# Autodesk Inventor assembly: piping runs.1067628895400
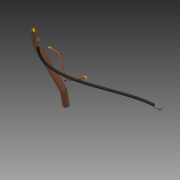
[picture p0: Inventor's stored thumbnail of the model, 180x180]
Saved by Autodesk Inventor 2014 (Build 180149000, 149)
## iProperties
Name: Hydraulic Hose - SAE Flanged Connection
ActiveState: False
PipeType: Flexible Hose
Material: UnInitValue
Standard: UnInitValue
FittingMaterial: UnInitValue
FittingStandard: UnInitValue
RouteDirection90: UnInitValue
RouteDirection45: UnInitValue
DiameterType: Nominal
Diameter: 1/2
Schedule: ID=0.5
OD: 0.880 in
ID: 0.500 in
Ending: UnInitValue
RoundUpValue: 0.125 in
DefaultBendRadius: UnInitValue
BendRadius: 0.500 in
PipingComponentColor: As Material
PipeKey: v3#d489867e-ac9b-47ea-b952-0a1b885f66be#4
CouplingKey: UnInitValue
StartFittingKey: v3#933069c9-73b6-4141-af99-628d4a97b2c2#1
EndFittingKey: v3#933069c9-73b6-4141-af99-628d4a97b2c2#1
Elbow90Key: UnInitValue
Elbow45Key: UnInitValue
SuppressStartFitting: False
SuppressEndFitting: False
UseSubASM: True
_ComponentInfo: <CS><C N="Pipe" R="1.117600" OR="1.117600" IR="0.635000" PL="PL" PartType="pipe" SymKey="" PN="Parker Hydraulic Hose - No Skive 1/2"><CO N="1"><FE V="0"/><FD V=
FlangeKey: UnInitValue
Gap: UnInitValue
GasketKey: UnInitValue
IsButtWelded: UnInitValue
IsFlanged: UnInitValue
MixedUnits: UnInitValue
ShowGap: UnInitValue
UseFlangsForCouplings: UnInitValue
Angle: UnInitValue
ElbowCustomKey: UnInitValue
IsSelfDraining: UnInitValue
Name: Hydraulic Hose - Male Taper Thread
StartFittingKey: v3#c8250148-a7b6-458b-b7bd-3b56763ca7cc#11
EndFittingKey: v3#c8250148-a7b6-458b-b7bd-3b56763ca7cc#11
Name: JIS G 3458/JIS B 2316 -  Welded Steel Pipe and Fittings
PipeType: Rigid Pipe
RouteDirection90: True
RouteDirection45: True
Diameter: M40
Schedule: 80
OD: UnInitValue
ID: UnInitValue
IntermediateSegmentsMin: 2.362 in
IntermediateSegmentsMax: 196.850 in
IntermediateSegmentsInc: 0.039 in
TerminationSegmentsMin: 2.362 in
TerminationSegmentsMax: 196.850 in
TerminationSegmentsInc: 0.039 in
PipeKey: v3#da14b0ab-0b36-4851-8d66-8c9cd0bcbe86#23
CouplingKey: v3#12b64993-10e6-4915-8315-0c0cce209ad0#16
Elbow90Key: v3#1f65ece3-c41a-48d4-8661-909ed34ade86#16
Elbow45Key: v3#28e76e79-e22c-40ab-8be2-ff545b1407c5#16
_ComponentInfo: <CS><C N="Pipe" R="2.430000" OR="2.430000" IR="1.920000" PL="PL" PartType="pipe" SymKey="" PN="JIS G 3458 Pipe 40 A x Sch 80"><CO N="1"><FE V="2"/><FD V="1"/><E
BendRadius: UnInitValue
EndFittingKey: UnInitValue
IsButtWelded: False
IsFlanged: False
MixedUnits: False
RoundUpValue: UnInitValue
StartFittingKey: UnInitValue
SuppressEndFitting: UnInitValue
SuppressStartFitting: UnInitValue
UseSubASM: UnInitValue
IsSelfDraining: False
Name: Hydraulic Hose - Male Straight Thread
StartFittingKey: v3#b50cb43e-68c0-48ac-8e25-7ef224ce0e6c#3
EndFittingKey: v3#b50cb43e-68c0-48ac-8e25-7ef224ce0e6c#3
Name: Hydraulic Hose - No Fittings
SuppressStartFitting: True
SuppressEndFitting: True
Diameter: 6
Elbow90Key: v3#97ecdcaf-8aa3-4fb0-8b6a-3da783de2ad5#108
Gap: 0.062 in
IntermediateSegmentsInc: 0.000 in
IntermediateSegmentsMax: 200.000 in
IntermediateSegmentsMin: 3.000 in
IsButtWelded: True
Name: ASTM A 53/A-ASME B16.9 - Steel Butt Welded Pipe
PipeKey: v3#4ce5e9fa-6da0-4801-ac02-ee7a0fb518d6#77
RouteDirection45: False
Schedule: 40
ShowGap: True
TerminationSegmentsInc: 0.000 in
TerminationSegmentsMax: 200.000 in
TerminationSegmentsMin: 3.000 in
_ComponentInfo: <CS><C N="Pipe" R="8.413750" OR="8.413750" IR="7.702550" PL="PL" PartType="pipe" SymKey="" PN="ASTM A 53/A 53M Pipe 6 - Schedule 40"><CO N="1"><FE V="2"/><FD V=
Company: Autodesk, Inc.
Name: ASME B36.10M-ASME B16.11 - Steel Threaded Pipe
Schedule: 30
IntermediateSegmentsMin: 2.000 in
IntermediateSegmentsInc: 0.100 in
TerminationSegmentsMin: 2.000 in
TerminationSegmentsInc: 0.100 in
PipeKey: v3#4a736116-503a-44ad-a922-868ac6b46736#1
CouplingKey: v3#52ad3977-2b89-4007-a6a6-7626bac0ae85#4
Elbow90Key: v3#160eac10-3e6f-4b5c-839c-61eee0d373dc#4
Elbow45Key: v3#5c2ab816-abcb-49a6-a106-4733af000f51#4
_ComponentInfo: <CS><C N="Pipe" R="1.066800" OR="1.066800" IR="0.825500" PL="PL" PartType="pipe" SymKey="" PN="ASME B36.10M Pipe with Threaded Ends 1/2 - Schedule 30"><CO N="1"
Name: ASTM A53/A53M-ASME B16.11 - Welded Steel Pipe
IntermediateSegmentsMin: 1.000 in
TerminationSegmentsMin: 1.000 in
PipeKey: v3#4ce5e9fa-6da0-4801-ac02-ee7a0fb518d6#7
CouplingKey: v3#ed415c76-4cec-44a3-ba67-72e47bf70384#4
Elbow90Key: v3#82a08401-12d7-413b-b7f9-9cf3b607be7b#4
Elbow45Key: v3#2e5fd082-3851-4eb0-bde1-6c7078a7d72b#4
_ComponentInfo: <CS><C N="Pipe" R="1.066800" OR="1.066800" IR="0.789940" PL="PL" PartType="pipe" SymKey="" PN="ASTM A 53/A 53M Pipe 1/2 - Schedule 40"><CO N="1"><FE V="2"/><FD 
Name: ISO 2531 - Flanged Ductile Iron Pipe and Fittings
Schedule: PN10
IntermediateSegmentsMin: 39.370 in
IntermediateSegmentsMax: 354.331 in
IntermediateSegmentsInc: 0.394 in
TerminationSegmentsMin: 39.370 in
TerminationSegmentsMax: 354.331 in
TerminationSegmentsInc: 0.394 in
PipeKey: v3#f52fbdcb-ece8-4303-8b76-5dbe8c7f2f9c#16
Elbow90Key: v3#451ae64e-c79d-4cba-b533-c09b8090ecb2#1
Elbow45Key: v3#81684a3f-f2a4-4fe6-95b1-f067ddead22f#1
_ComponentInfo: <CS><C N="Pipe" R="2.700000" OR="2.700000" IR="2.000000" PL="PL" PartType="pipe" SymKey="" PN="ISO 2531 Pipe with Integrally Cast Flanges DN40 PN 10"><CO N="1">
Name: Hydraulic Hose - Female Thread - Swivel
StartFittingKey: v3#c5e461f5-5e73-4f2e-8c1e-4358d4d6f46c#4
EndFittingKey: v3#c5e461f5-5e73-4f2e-8c1e-4358d4d6f46c#4
USE_R9_BOM: False
TPVersion: 11.0.2
Name: DIN 2458/DIN 2605 - Welded Steel Pipe and Fittings
Schedule: ID=30.7
PipeKey: v3#dcef2839-8903-4c98-a96c-b861f5d9bb7f#98
Elbow90Key: v3#ace818b0-7b7c-4ad9-b19c-6da358a202c1#17
Elbow45Key: v3#97879d80-057e-491b-840b-74a9b3a7cf63#17
_ComponentInfo: <CS><C N="Pipe" R="2.415000" OR="2.415000" IR="1.535000" PL="PL" PartType="pipe" SymKey="" PN="DIN 2458 Pipe 48.3 x 8.8"><CO N="1"><FE V="2"/><FD V="0"/><ET V="
Control State: 0
Master: False
Checked Out: False
Angle: 92.00 deg
Diameter: 1
Elbow45Key: v3#bf26aa2a-f3dd-474c-8758-922a145c2b02#15
Elbow90Key: v3#3e93288f-9bb7-4e46-9d6b-544f8c20ca1c#3
ElbowCustomKey: v3#1f3bd44a-47ab-42f9-b3e0-74afa0c3f0ca#3
Gap: 0.094 in
IsSelfDraining: True
Name: ASME BPE - Butt Welded
PipeKey: v3#b10c956f-6fc6-429e-8056-0864a8581764#39
Schedule: ID=0.76
_ComponentInfo: <CS><C N="Pipe" R="1.270000" OR="1.270000" IR="0.965200" PL="PL" PartType="pipe" SymKey="" PN="ASTM A 269 Tube with Welded ends 1 x 0.12"><CO N="1"><FE V="2"/><
Elbow90Key: v3#6a678020-d9d9-4685-bba9-906b9a167083#10
FlangeKey: v3#24991861-26e3-4c21-a713-f46e314eddd5#10
GasketKey: v3#2a41914c-f5fb-4682-9c6a-1870d826d3d0#23
IsFlanged: True
Name: ASTM A 53/A 53M - Butt Welded/Flanged Steel Pipe
UseFlangsForCouplings: False
Name: JIS G 3442/JIS B 2301 Threaded Steel Pipe and Iron Fittings
Schedule: ID=16.1
IntermediateSegmentsMin: 0.787 in
TerminationSegmentsMin: 0.787 in
PipeKey: v3#9964fba4-9d5a-4d75-85a8-e38022ccdce1#2
CouplingKey: v3#181262db-c004-4877-bc40-c64b931a44f6#3
Elbow90Key: v3#6c92b367-65e9-486b-b952-db434ae2548d#3
Elbow45Key: v3#960407aa-00b9-4d72-aae7-d50595845cfd#3
_ComponentInfo: <CS><C N="Pipe" R="1.085000" OR="1.085000" IR="0.805000" PL="PL" PartType="pipe" SymKey="" PN="JIS G 3442 Pipe with Threaded Ends 21.7 x 2.8"><CO N="1"><FE V="0
Name: Large Copper Tubing
PipeType: Tubing
Diameter: 2
Schedule: L
IntermediateSegmentsMin: 0.000 in
IntermediateSegmentsMax: 100.000 in
TerminationSegmentsMin: 0.000 in
TerminationSegmentsMax: 100.000 in
DefaultBendRadius: 2.000 in
PipeKey: V3#44B182C9-4BCE-4825-BB4D-596143122252#24
CouplingKey: V3#0DC1AE02-7BBF-4CCF-8498-581434B0A765#8
_ComponentInfo: <CS><C N="Pipe" R="2.698750" OR="2.698750" IR="2.520950" PL="PL" PartType="pipe" SymKey="" PN="ASTM B 88 Tube 2 - Type L"><CO N="1"><FE V="0"/><FD V="0"/><ET V=
Part Number: piping runs.1067628895400
Document SubType Name: Tube & Pipe
Created: 2003-10
Designer: Autodesk, Inc.
Manufacturer: Standard
Standards Organization: Custom
Mass: 2522.31 g
Surface Area: 4231.74 cm^2
Volume: 561.258 cm^3
Density: 4.49403 g/cm^3
Name: ASTM B 88-ASME B16.22 - Soldered Copper Tubing
ActiveState: True
PipeKey: v3#44b182c9-4bce-4825-bb4d-596143122252#7
CouplingKey: v3#0dc1ae02-7bbf-4ccf-8498-581434b0a765#3
_ComponentInfo: <CS><C N="Pipe" R="0.793750" OR="0.793750" IR="0.692150" PL="PL" PartType="pipe" SymKey="" PN="ASTM B 88 Tube 1/2 - Type L"><CO N="1"><FE V="0"/><FD V="0"/><ET 
Shininess: 64.0
Length Units: 11272
Angle Units: 11279
Time Units: 11290
Mass Units: 11286
Length Display Precision: 3
Angle Display Precision: 2
Compacted: True
Name: ISO 7598/ISO 49 - Threaded Steel Pipe with Iron Fittings
PipeKey: v3#1052637f-74b5-47f4-adeb-d4e8d3fa53b8#1
CouplingKey: v3#7e56b2cb-a132-4546-b8a7-a14538454b94#3
Elbow90Key: v3#b72bb08b-ad33-47cc-a03d-7f3d76c6616b#3
Elbow45Key: v3#a96c5204-26e4-4bb2-b8f1-f0623fbc94bb#2
_ComponentInfo: <CS><C N="Pipe" R="1.065000" OR="1.065000" IR="0.805000" PL="PL" PartType="pipe" SymKey="" PN="ISO 7598 Tube with Threaded Ends DN15"><CO N="1"><FE V="0"/><FD V
Density: 0.0
Volumn: 0.0
Area: 0.0
PropertySet Name: Model Information
Name: Hydraulic Hose - Female Taper Thread
StartFittingKey: v3#cc3bd835-95a2-497d-9893-176cd9c426f6#6
EndFittingKey: v3#cc3bd835-95a2-497d-9893-176cd9c426f6#6
FlangeKey: v3#c11442d2-c568-438f-a870-8ac9b5b636cb#10
Name: ASTM A 53/A-ASME B16.5 - Flanged Steel Threaded Pipe
PipeKey: v3#c5bd7d28-cdb3-4507-9f3d-c2787d93fe8a#40
_ComponentInfo: <CS><C N="Pipe" R="8.413750" OR="8.413750" IR="7.702550" PL="PL" PartType="pipe" SymKey="" PN="ASTM A 53/A 53M Pipe with Threaded Ends 6 - Schedule 40"><CO N="1
Name: ANSI/ASME B36.19M-ASME B16.3 - Threaded Pipe with Iron Fittings
Schedule: 40S
PipeKey: v3#323c0148-c750-449d-a0c6-11721f2a5046#1
CouplingKey: v3#771d4942-b9e7-43bc-9d41-ab12a9580492#3
Elbow90Key: v3#bc6b44ab-9235-4590-b699-74498030a1ff#3
Elbow45Key: v3#626cc28c-1a24-4045-be0d-40d896dc828d#3
_ComponentInfo: <CS><C N="Pipe" R="1.066800" OR="1.066800" IR="0.789940" PL="PL" PartType="pipe" SymKey="" PN="ANSI/ASME B36.19M Pipe with Threaded Ends 1/2 - Schedule 40S"><CO
Name: DIN 2458/DIN EN 10242 - Threaded Steel Pipe and Iron Fittings
Schedule: ID=12.3
PipeKey: v3#d689fd5f-ac5a-46d7-a883-3089b2f6e0a4#28
CouplingKey: v3#d2599e7a-1865-48da-a234-5418a1cd5dfe#3
Elbow90Key: v3#9fba244e-81ed-4fc6-a9ac-7eb372fa3ffe#3
Elbow45Key: v3#6ce5b1be-37aa-4928-b23a-0df64e6ddf38#2
_ComponentInfo: <CS><C N="Pipe" R="1.065000" OR="1.065000" IR="0.615000" PL="PL" PartType="pipe" SymKey="" PN="DIN 2458 Pipe with Threaded Ends 21.3 x 4.5"><CO N="1"><FE V="0"/
Name: ASTM D 1785-ASTM D 2466 - Jointed PVC Pipe and Fittings
PipeKey: v3#4bf12049-4375-491b-8f13-d4ee0c517c57#1
CouplingKey: v3#29993622-4c6a-437e-8b8c-43a0846f8735#1
Elbow90Key: v3#25d2a8db-6517-4627-a5a4-9d27e4d26b9b#1
Elbow45Key: v3#d7b5d569-4a12-4d65-ba55-12203d6ac7ed#1
_ComponentInfo: <CS><C N="Pipe" R="1.066800" OR="1.066800" IR="0.789940" PL="PL" PartType="pipe" SymKey="" PN="ASTM D 1785 Pipe 1/2 - Schedule 40"><CO N="1"><FE V="0"/><FD V="0
Name: JIS K 6741/JIS K 6739 - Jointed PVC-U Pipe and Fittings
Schedule: VP
IntermediateSegmentsMax: 98.425 in
TerminationSegmentsMax: 98.425 in
PipeKey: v3#45338dd0-af69-48c0-a2ed-8ade33a08701#5
CouplingKey: v3#eaa8de87-dc67-4eca-ba7e-4267a30f8f7f#2
Elbow90Key: v3#c4513a61-3106-4a78-baf9-a1badd100245#2
Elbow45Key: v3#2769403e-a4fd-4a4c-8e4c-659ea845bd78#2
_ComponentInfo: <CS><C N="Pipe" R="2.400000" OR="2.400000" IR="2.040000" PL="PL" PartType="pipe" SymKey="" PN="JIS K 6741 Pipe VP 40"><CO N="1"><FE V="0"/><FD V="1"/><ET V="Joi
count: 30
Name: DIN 8062/DIN 8063 - Jointed PVC-U Pipe and Fittings
Schedule: 5
PipeKey: v3#3d294dc7-89c3-4c37-a0ae-28c15a73bfd0#13
CouplingKey: v3#3edf83e2-464b-4b31-84c5-c329ffbf2a4f#5
Elbow90Key: v3#fbd68fd5-590c-4cb5-8c20-9e9bdd396a04#5
Elbow45Key: v3#2f597a97-b15b-49d4-87cb-7bfe69eb62ee#5
_ComponentInfo: <CS><C N="Pipe" R="2.000000" OR="2.000000" IR="1.700000" PL="PL" PartType="pipe" SymKey="" PN="DIN 8062 Pipe 40 x 3"><CO N="1"><FE V="0"/><FD V="0"/><ET V="Join
CouplingKey: V3#181262DB-C004-4877-BC40-C64B931A44F6#7
Diameter: 1 1/2
Elbow45Key: V3#960407AA-00B9-4D72-AAE7-D50595845CFD#7
Elbow90Key: V3#6C92B367-65E9-486B-B952-DB434AE2548D#7
Name: JIS 50A
PipeKey: V3#9964FBA4-9D5A-4D75-85A8-E38022CCDCE1#6
Schedule: ID=41.6
_ComponentInfo: <CS><C N="Pipe" R="2.430000" OR="2.430000" IR="2.080000" PL="PL" PartType="pipe" SymKey="" PN="JIS G 3442 Pipe with Threaded Ends 48.6 x 3.5"><CO N="1"><FE V="0
Name: ISO 4065-ISO 3633 - PVC Pipe and Fittings
Schedule: S40
PipeKey: v3#4f84f716-5ba0-45ef-967a-c32c3d7345ce#70
CouplingKey: v3#b06656e5-2b55-488c-bcf0-6a90c79c4683#2
Elbow90Key: v3#17490b17-1dd8-40fc-8de7-1a70c3bab2d7#1
Elbow45Key: v3#421a8b99-1721-409a-bc3b-c00889561754#1
_ComponentInfo: <CS><C N="Pipe" R="2.000000" OR="2.000000" IR="1.950000" PL="PL" PartType="pipe" SymKey="" PN="ISO 4065 Pipe DN40x0.5xS40"><CO N="1"><FE V="0"/><FD V="0"/><ET V
Author: Autodesk, Inc.
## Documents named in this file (4)
- C:\Users\iTools\Desktop\tutorial files\Tube and Pipe\Accumulator\AIP\piping runs.1067628895400.iam
- C:\Users\iTools\Desktop\tutorial files\Tube and Pipe\Accumulator\AIP\Run1\Tube Run1.iam
- C:\Users\iTools\Desktop\tutorial files\Tube and Pipe\Accumulator\AIP\Hose Run1\Hose Run1.iam
- C:\Users\iTools\Desktop\tutorial files\Tube and Pipe\Accumulator\AIP\Run2\Tube Run2.iam
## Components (3 placed, 3 different names)
1. Pipe Run 1 [sub-assembly]
2. Pipe Run 2 [sub-assembly]
3. Hose Run 1 [sub-assembly]
